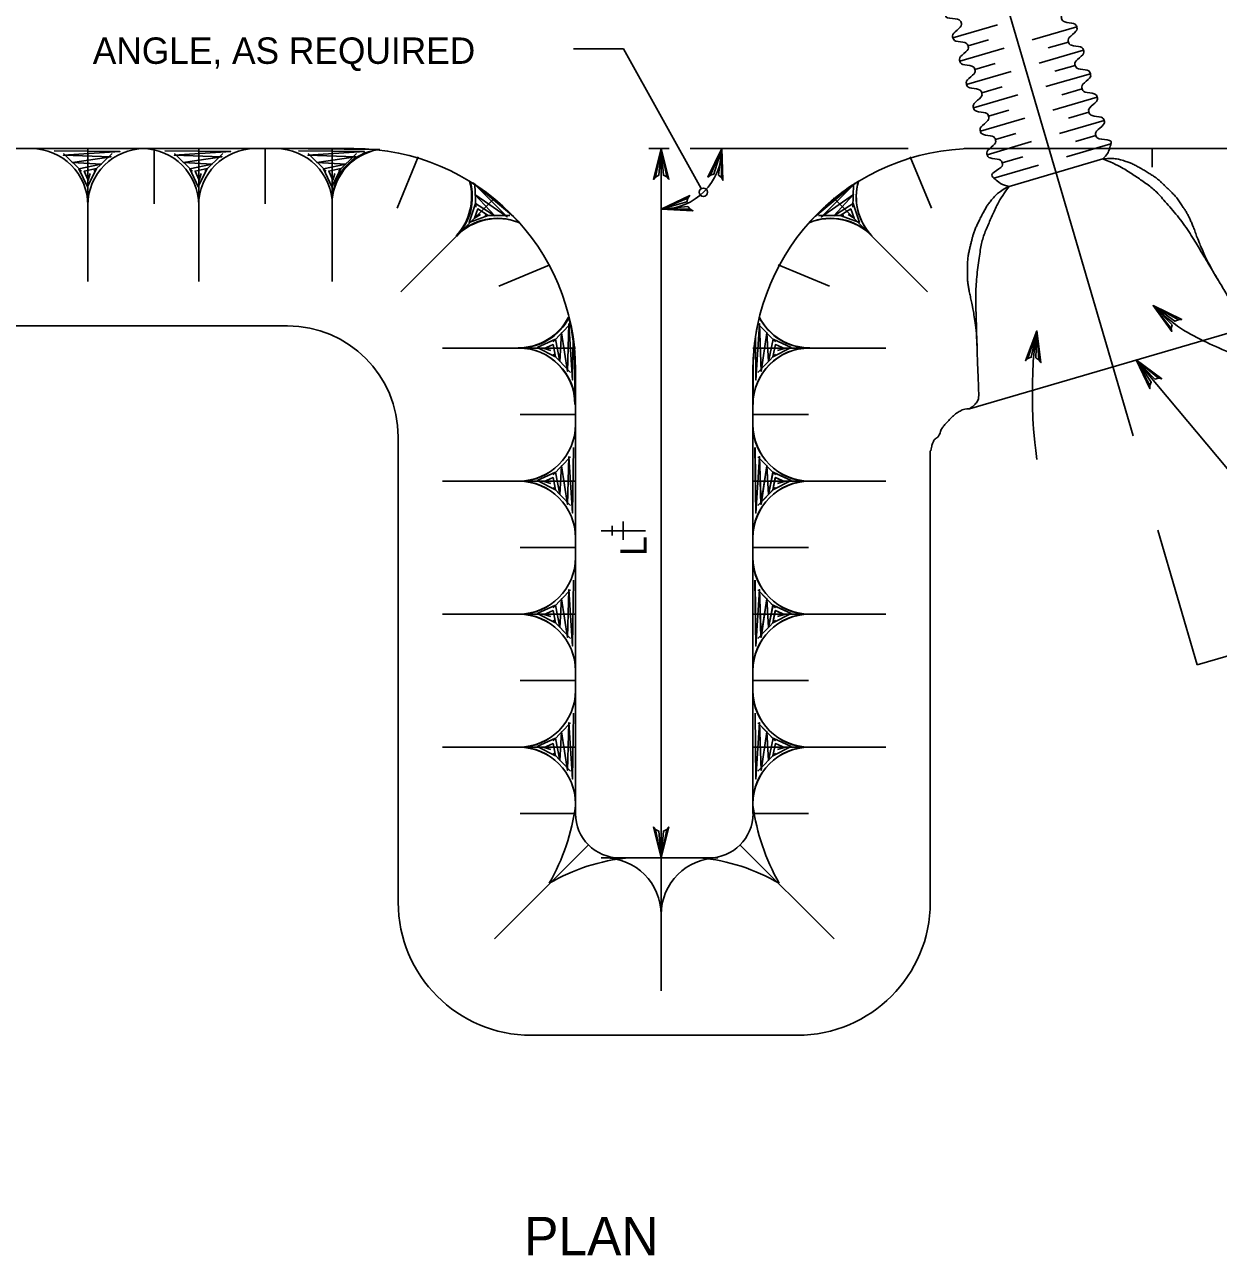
# Model space of a CAD drawing. Extents: x 636462 to 637367, y 299944 to 300538.
# Drawn here: x 636619.2 to 636754.8, y 300214.8 to 300354.6 of the extents above; entities that cross this region are included whole.
import ezdxf

# ---------------------------------------------------------------- set-up
doc = ezdxf.new("R2010")
doc.units = 0
doc.layers.add('1', color=7, linetype='Continuous')
doc.layers.add('Default', color=7, linetype='Continuous')

# ---------------------------------------------------------------- blocks, each defined once
blk = doc.blocks.new('SC9446')
at = {"layer": 'Default'}
blk.add_line((0, 0), (0, 0), dxfattribs=at)
blk = doc.blocks.new('CROSS')
at = {"layer": 'Default'}
for p, q in [((0, 0.436), (0, -0.435)), ((0, 0.436), (0, 0)), ((-0.182, 0), (0, 0)), ((-0.096, 0.218), (0, 0.218)), ((0, 0.218), (0.096, 0.218)), ((0, 0), (0.182, 0))]:
    blk.add_line(p, q, dxfattribs=at)

msp = doc.modelspace()

# ---------------------------------------------------------------- linework, layer by layer
at = {"layer": '1'}
for p, q in [((636686.8, 300259.95), (636685.04, 300259.95)), ((636696.87, 300259.95), (636686.8, 300259.95))]:
    msp.add_line(p, q, dxfattribs=at)
for centre, radius, start, end in [((636657.2, 300269.28), 24.8, 330.4999, 352.1576), ((636686.8, 300264.99), 5.04, 180, 270), ((636696.88, 300264.99), 5.04, 270, 0), ((636726.48, 300269.28), 24.8, 187.8423, 209.5001), ((636689.86, 300238.02), 22.04, 95.5213, 120.1887), ((636685.04, 300253.51), 6.44, 0, 90), ((636697.93, 300253.51), 6.44, 90, 180), ((636693.81, 300238.02), 22.04, 59.8113, 84.4787)]:
    msp.add_arc(centre, radius, start, end, dxfattribs=at)
at = {"layer": 'Default'}
for p, q in [((636730.38, 300358.11), (636745.08, 300307.89)), ((636724.62, 300353.13), (636729.68, 300354.61)), ((636733.63, 300352.88), (636738.69, 300354.36)), ((636726.34, 300352.19), (636728.66, 300352.87)), ((636725.4, 300350.47), (636730.45, 300351.95)), ((636734.41, 300350.22), (636739.46, 300351.7)), ((636735.43, 300351.96), (636737.75, 300352.64)), ((636727.12, 300349.53), (636729.44, 300350.21)), ((636736.21, 300349.31), (636738.52, 300349.99)), ((636726.18, 300347.82), (636731.23, 300349.29)), ((636735.19, 300347.57), (636740.24, 300349.04)), ((636727.9, 300346.88), (636730.22, 300347.55)), ((636736.99, 300346.65), (636739.3, 300347.33)), ((636726.96, 300345.16), (636732.01, 300346.64)), ((636735.97, 300344.91), (636741.02, 300346.39)), ((636728.68, 300344.22), (636730.99, 300344.89)), ((636737.76, 300343.99), (636740.08, 300344.67)), ((636727.74, 300342.5), (636732.79, 300343.98)), ((636736.75, 300342.25), (636741.8, 300343.73)), ((636729.45, 300341.56), (636731.77, 300342.24)), ((636738.54, 300341.33), (636740.86, 300342.01)), ((636589.35, 300340.53), (636632.71, 300340.53)), ((636632.81, 300340.53), (636619.57, 300340.53)), ((636619.57, 300340.53), (636619.93, 300340.53)), ((636626.37, 300340.53), (636626.37, 300325.42)), ((636645.4, 300340.53), (636632.16, 300340.53)), ((636632.16, 300340.53), (636632.52, 300340.53)), ((636632.71, 300340.53), (636656.58, 300340.53)), ((636633.92, 300340.53), (636633.92, 300334.24)), ((636638.96, 300340.53), (636638.96, 300325.42)), ((636646.51, 300340.53), (636646.51, 300334.24)), ((636659.53, 300340.42), (636647.34, 300340.53)), ((636647.34, 300340.53), (636647.7, 300340.53)), ((636654.14, 300340.53), (636654.14, 300325.42)), ((636692.38, 300340.53), (636690.08, 300340.53)), ((636691.49, 300340.53), (636691.49, 300259.95)), ((636719.55, 300340.53), (636694.79, 300340.53)), ((636725.91, 300340.53), (636841.16, 300340.53)), ((636727.09, 300340.53), (636738.5, 300340.53)), ((636728.51, 300339.84), (636733.57, 300341.32)), ((636737.53, 300339.59), (636742.58, 300341.07)), ((636747.24, 300340.53), (636747.24, 300338.43)), ((636623.61, 300339.97), (636625.66, 300337.98)), ((636629.13, 300339.97), (636627.07, 300337.98)), ((636636.2, 300339.97), (636638.25, 300337.98)), ((636641.72, 300339.97), (636639.66, 300337.98)), ((636651.38, 300339.97), (636653.43, 300337.98)), ((636656.9, 300339.97), (636654.85, 300337.98)), ((636663.9, 300339.58), (636661.49, 300333.76)), ((636719.78, 300339.58), (636722.19, 300333.76)), ((636730.23, 300338.9), (636732.55, 300339.58)), ((636731.01, 300336.24), (636741.64, 300339.35)), ((636729.29, 300337.18), (636734.34, 300338.66)), ((636670.33, 300336.45), (636670.43, 300333.89)), ((636713.35, 300336.45), (636713.25, 300333.89)), ((636672.52, 300334.85), (636661.93, 300324.25)), ((636711.07, 300334.94), (636721.75, 300324.25)), ((636674.31, 300332.95), (636671.45, 300332.92)), ((636709.37, 300332.95), (636712.23, 300332.92)), ((636678.77, 300327.27), (636673.07, 300324.9)), ((636704.79, 300327.31), (636710.61, 300324.9)), ((636681.2, 300320.63), (636679.21, 300318.58)), ((636702.48, 300320.63), (636704.46, 300318.58)), ((636589.35, 300320.39), (636649.03, 300320.39)), ((636726.5, 300310.97), (636759.06, 300320.5)), ((636681.77, 300317.87), (636666.66, 300317.87)), ((636701.91, 300317.87), (636717.02, 300317.87)), ((636681.2, 300315.11), (636679.21, 300317.16)), ((636702.48, 300315.11), (636704.46, 300317.16)), ((636681.7, 300315.38), (636681.7, 300311.46)), ((636681.77, 300315.35), (636681.77, 300264.99)), ((636701.91, 300315.35), (636701.91, 300264.99)), ((636701.92, 300315.38), (636701.92, 300311.46)), ((636681.77, 300310.31), (636675.47, 300310.31)), ((636681.77, 300296.3), (636681.77, 300309.54)), ((636681.77, 300309.54), (636681.77, 300309.18)), ((636701.89, 300296.3), (636701.89, 300309.54)), ((636701.89, 300309.54), (636701.89, 300309.18)), ((636701.91, 300310.31), (636708.21, 300310.31)), ((636661.62, 300307.8), (636661.62, 300254.92)), ((636681.2, 300305.52), (636679.21, 300303.47)), ((636681.2, 300305.52), (636679.21, 300303.47)), ((636702.48, 300305.52), (636704.46, 300303.47)), ((636722.06, 300306.19), (636722.06, 300254.92)), ((636681.77, 300302.76), (636666.66, 300302.76)), ((636701.91, 300302.76), (636717.02, 300302.76)), ((636681.2, 300300), (636679.21, 300302.05)), ((636702.46, 300300), (636704.44, 300302.05)), ((636702.48, 300300), (636704.46, 300302.05)), ((636747.9, 300297.2), (636752.38, 300281.88)), ((636681.77, 300295.21), (636675.47, 300295.21)), ((636681.77, 300281.19), (636681.77, 300294.43)), ((636681.77, 300294.43), (636681.77, 300294.07)), ((636701.89, 300281.19), (636701.89, 300294.43)), ((636701.89, 300294.43), (636701.89, 300294.07)), ((636701.91, 300295.21), (636708.21, 300295.21)), ((636681.2, 300290.41), (636679.21, 300288.36)), ((636681.2, 300290.41), (636679.21, 300288.36)), ((636702.46, 300290.41), (636704.44, 300288.36)), ((636702.46, 300290.41), (636704.44, 300288.36)), ((636702.48, 300290.41), (636704.46, 300288.36)), ((636681.77, 300287.65), (636666.66, 300287.65)), ((636701.91, 300287.65), (636717.02, 300287.65)), ((636681.2, 300284.89), (636679.21, 300286.95)), ((636702.48, 300284.89), (636704.46, 300286.95)), ((636752.38, 300281.88), (636762.67, 300284.89)), ((636681.77, 300280.1), (636675.47, 300280.1)), ((636701.91, 300280.1), (636708.21, 300280.1)), ((636681.77, 300266.08), (636681.77, 300279.32)), ((636681.77, 300279.32), (636681.77, 300278.96)), ((636701.89, 300266.08), (636701.89, 300279.32)), ((636701.89, 300279.32), (636701.89, 300278.96)), ((636681.2, 300275.3), (636679.21, 300273.25)), ((636702.46, 300275.3), (636704.44, 300273.25)), ((636702.48, 300275.3), (636704.46, 300273.25)), ((636681.77, 300272.54), (636666.66, 300272.54)), ((636681.2, 300269.79), (636679.21, 300271.84)), ((636701.91, 300272.54), (636717.02, 300272.54)), ((636702.48, 300269.79), (636704.46, 300271.84)), ((636681.77, 300264.99), (636675.47, 300264.99)), ((636701.91, 300264.99), (636701.91, 300265.89)), ((636701.91, 300264.99), (636708.21, 300264.99)), ((636683.24, 300261.43), (636672.56, 300250.74)), ((636700.44, 300261.43), (636711.12, 300250.74)), ((636697.93, 300259.95), (636684.68, 300259.95)), ((636684.68, 300259.95), (636685.04, 300259.95)), ((636686.8, 300259.95), (636687.74, 300259.95)), ((636686.8, 300259.95), (636687.74, 300259.95)), ((636691.49, 300259.95), (636691.49, 300244.84)), ((636695.93, 300259.95), (636696.88, 300259.95)), ((636676.73, 300239.81), (636706.95, 300239.81))]:
    msp.add_line(p, q, dxfattribs=at)
for points in [[(636696.04, 300335.99), (636687.2, 300351.85), (636681.53, 300351.85)], [(636622.53, 300340.29), (636630.01, 300340.19), (636623.59, 300339.78), (636629.01, 300339.61), (636624.62, 300338.94), (636627.89, 300338.75), (636625.36, 300338.24), (636626.32, 300336.18), (636627.35, 300338.27), (636625.97, 300337.98), (636626.42, 300336.95), (636626.64, 300337.72)], [(636635.12, 300340.29), (636642.6, 300340.19), (636636.18, 300339.78), (636641.6, 300339.61), (636637.21, 300338.94), (636640.48, 300338.75), (636637.95, 300338.24), (636638.91, 300336.18), (636639.94, 300338.27), (636638.56, 300337.98), (636639.01, 300336.95), (636639.23, 300337.72)], [(636650.31, 300340.29), (636657.78, 300340.19), (636651.37, 300339.78), (636656.79, 300339.61), (636652.39, 300338.94), (636655.66, 300338.75), (636653.13, 300338.24), (636654.09, 300336.18), (636655.12, 300338.27), (636653.74, 300337.98), (636654.19, 300336.95), (636654.41, 300337.72)], [(636690.85, 300337.3), (636690.63, 300337.03), (636691.49, 300340.53), (636690.85, 300337.3), (636691.22, 300337.5), (636691.49, 300340.53), (636691.74, 300337.5), (636692.12, 300337.32), (636691.49, 300340.53), (636692.37, 300337.04), (636692.12, 300337.32)], [(636697.08, 300337.51), (636696.8, 300337.29), (636698.38, 300340.53), (636697.08, 300337.51), (636697.48, 300337.62), (636698.38, 300340.53), (636698, 300337.52), (636698.33, 300337.26), (636698.38, 300340.53), (636698.51, 300336.93), (636698.33, 300337.26)], [(636674.71, 300332.83), (636670.17, 300336.62), (636673.99, 300332.77), (636670.34, 300335.31), (636672.58, 300332.91), (636670.39, 300334.29), (636669.67, 300332.14), (636671.85, 300332.94), (636670.65, 300333.68), (636670.27, 300332.63), (636670.96, 300333.03)], [(636708.97, 300332.83), (636713.51, 300336.62), (636709.69, 300332.77), (636713.34, 300335.31), (636711.1, 300332.91), (636713.29, 300334.29), (636714.01, 300332.14), (636711.83, 300332.94), (636713.03, 300333.68), (636713.41, 300332.63), (636712.72, 300333.03)], [(636694.78, 300333.64), (636695.09, 300333.48), (636691.49, 300333.64), (636694.78, 300333.64), (636694.51, 300333.97), (636691.49, 300333.64), (636694.41, 300334.48), (636694.51, 300334.89), (636691.49, 300333.64), (636694.74, 300335.19), (636694.51, 300334.89)], [(636749.42, 300320.11), (636749.48, 300319.76), (636747.37, 300322.69), (636749.42, 300320.11), (636749.51, 300320.52), (636747.37, 300322.69), (636749.85, 300320.92), (636750.23, 300321.09), (636747.37, 300322.69), (636750.61, 300321.1), (636750.23, 300321.09)], [(636681.49, 300319.08), (636681.43, 300314.23), (636681.01, 300320.64), (636680.85, 300315.22), (636680.18, 300319.62), (636679.98, 300316.35), (636679.47, 300318.88), (636677.42, 300317.92), (636679.5, 300316.89), (636679.21, 300318.27), (636678.19, 300317.82), (636678.96, 300317.6)], [(636702.19, 300319.08), (636702.25, 300314.23), (636702.67, 300320.64), (636702.83, 300315.22), (636703.5, 300319.62), (636703.69, 300316.35), (636704.21, 300318.88), (636706.26, 300317.92), (636704.17, 300316.89), (636704.46, 300318.27), (636705.49, 300317.82), (636704.72, 300317.6)], [(636733.14, 300316.67), (636732.88, 300316.43), (636734.16, 300319.81), (636733.14, 300316.67), (636733.53, 300316.82), (636734.16, 300319.81), (636734.05, 300316.77), (636734.4, 300316.54), (636734.16, 300319.81), (636734.62, 300316.23), (636734.4, 300316.54)], [(636745.45, 300316.52), (636758.15, 300301.36), (636763.81, 300301.36)], [(636747, 300313.61), (636747, 300313.26), (636745.45, 300316.52), (636747, 300313.61), (636747.16, 300314), (636745.45, 300316.52), (636747.57, 300314.34), (636747.97, 300314.44), (636745.45, 300316.52), (636748.35, 300314.38), (636747.97, 300314.44)], [(636681.52, 300306.59), (636681.43, 300299.12), (636681.01, 300305.53), (636680.85, 300300.11), (636680.18, 300304.51), (636679.98, 300301.24), (636679.47, 300303.77), (636677.42, 300302.81), (636679.5, 300301.78), (636679.21, 300303.16), (636678.19, 300302.71), (636678.96, 300302.49)], [(636702.13, 300306.59), (636702.23, 300299.12), (636702.65, 300305.53), (636702.81, 300300.11), (636703.48, 300304.51), (636703.67, 300301.24), (636704.19, 300303.77), (636706.24, 300302.81), (636704.16, 300301.78), (636704.44, 300303.16), (636705.47, 300302.71), (636704.7, 300302.49)], [(636702.15, 300306.59), (636702.25, 300299.12), (636702.67, 300305.53), (636702.83, 300300.11), (636703.5, 300304.51), (636703.69, 300301.24), (636704.21, 300303.77), (636706.26, 300302.81), (636704.17, 300301.78), (636704.46, 300303.16), (636705.49, 300302.71), (636704.72, 300302.49)], [(636681.52, 300291.49), (636681.43, 300284.01), (636681.01, 300290.43), (636680.85, 300285), (636680.18, 300289.4), (636679.98, 300286.13), (636679.47, 300288.66), (636677.42, 300287.7), (636679.5, 300286.67), (636679.21, 300288.05), (636678.19, 300287.6), (636678.96, 300287.38)], [(636702.13, 300291.49), (636702.23, 300284.01), (636702.65, 300290.43), (636702.81, 300285), (636703.48, 300289.4), (636703.67, 300286.13), (636704.19, 300288.66), (636706.24, 300287.7), (636704.16, 300286.67), (636704.44, 300288.05), (636705.47, 300287.6), (636704.7, 300287.38)], [(636702.15, 300291.49), (636702.25, 300284.01), (636702.67, 300290.43), (636702.83, 300285), (636703.5, 300289.4), (636703.69, 300286.13), (636704.21, 300288.66), (636706.26, 300287.7), (636704.17, 300286.67), (636704.46, 300288.05), (636705.49, 300287.6), (636704.72, 300287.38)], [(636681.52, 300276.38), (636681.43, 300268.9), (636681.01, 300275.32), (636680.85, 300269.9), (636680.18, 300274.29), (636679.98, 300271.02), (636679.47, 300273.55), (636677.42, 300272.59), (636679.5, 300271.56), (636679.21, 300272.94), (636678.19, 300272.49), (636678.96, 300272.27)], [(636702.15, 300276.38), (636702.25, 300268.9), (636702.67, 300275.32), (636702.83, 300269.9), (636703.5, 300274.29), (636703.69, 300271.02), (636704.21, 300273.55), (636706.26, 300272.59), (636704.17, 300271.56), (636704.46, 300272.94), (636705.49, 300272.49), (636704.72, 300272.27)], [(636692.12, 300263.18), (636692.35, 300263.45), (636691.49, 300259.95), (636692.12, 300263.18), (636691.75, 300262.99), (636691.49, 300259.95), (636691.23, 300262.98), (636690.85, 300263.16), (636691.49, 300259.95), (636690.6, 300263.45), (636690.85, 300263.16)]]:
    msp.add_lwpolyline(points, dxfattribs=at)
msp.add_circle((636696.28, 300335.57), 0.481, dxfattribs=at)
for centre, radius, start, end in [((636619.93, 300334.09), 6.44, 0, 90), ((636619.93, 300334.09), 6.44, 0, 90), ((636632.81, 300334.09), 6.44, 90, 180), ((636632.81, 300334.09), 6.44, 90, 180), ((636632.81, 300334.09), 6.44, 90, 180), ((636632.81, 300334.09), 6.44, 90, 180), ((636632.52, 300334.09), 6.44, 0, 90), ((636632.52, 300334.09), 6.44, 0, 90), ((636645.4, 300334.09), 6.44, 90, 180), ((636645.4, 300334.09), 6.44, 90, 180), ((636647.7, 300334.09), 6.44, 0, 90), ((636660.51, 300334.09), 6.44, 101.7661, 173.8515), ((636660, 300334.56), 5.88, 94.5668, 184.5668), ((636656.59, 300315.35), 25.18, 0, 90), ((636691.49, 300340.53), 6.9, 270, 0), ((636727.09, 300315.35), 25.18, 90, 180), ((636663.52, 300335.06), 6.44, 316.4347, 15.8913), ((636663.6, 300335.03), 6.44, 316.4347, 15.8913), ((636656.52, 300315.38), 25.18, 41.7104, 58.3729), ((636727.1, 300315.38), 25.18, 121.6271, 138.2896), ((636720.08, 300335.03), 6.44, 164.1087, 223.5653), ((636720.09, 300335.06), 6.44, 164.1087, 223.5653), ((636672.86, 300326.18), 6.44, 67.6038, 136.4347), ((636672.93, 300326.15), 6.44, 67.6038, 136.4347), ((636710.76, 300326.18), 6.44, 43.5653, 112.3962), ((636710.75, 300326.15), 6.44, 43.5653, 112.3962), ((636675.25, 300324.34), 6.44, 270, 332.5918), ((636675.32, 300324.31), 6.44, 270, 332.5918), ((636656.52, 300315.38), 25.18, 360, 13.7705), ((636727.1, 300315.38), 25.18, 166.2295, 180), ((636708.35, 300324.31), 6.44, 207.4082, 270), ((636708.36, 300324.34), 6.44, 207.4082, 270), ((636649.03, 300307.8), 12.59, 0, 90), ((636675.25, 300311.46), 6.44, 0, 90), ((636675.32, 300311.43), 6.44, 0, 90), ((636708.35, 300311.43), 6.44, 90, 180), ((636708.36, 300311.46), 6.44, 90, 180), ((636675.32, 300309.2), 6.44, 270, 0), ((636675.32, 300309.2), 6.44, 270, 0), ((636675.32, 300309.18), 6.44, 270, 360), ((636708.33, 300309.18), 6.44, 180, 270), ((636708.35, 300309.2), 6.44, 180, 270), ((636675.32, 300296.32), 6.44, 0, 90), ((636675.32, 300296.3), 6.44, 360, 90), ((636708.33, 300296.32), 6.44, 90, 180), ((636708.33, 300296.3), 6.44, 90, 180), ((636708.35, 300296.32), 6.44, 90, 180), ((636675.32, 300294.09), 6.44, 270, 0), ((636675.32, 300294.09), 6.44, 270, 0), ((636675.32, 300294.07), 6.44, 270, 360), ((636708.33, 300294.09), 6.44, 180, 270), ((636708.33, 300294.09), 6.44, 180, 270), ((636708.33, 300294.07), 6.44, 180, 270), ((636708.35, 300294.09), 6.44, 180, 270), ((636675.32, 300281.21), 6.44, 0, 90), ((636675.32, 300281.19), 6.44, 360, 90), ((636708.33, 300281.19), 6.44, 90, 180), ((636708.35, 300281.21), 6.44, 90, 180), ((636675.32, 300278.98), 6.44, 270, 0), ((636675.32, 300278.96), 6.44, 270, 360), ((636708.33, 300278.98), 6.44, 180, 270), ((636708.33, 300278.96), 6.44, 180, 270), ((636708.35, 300278.98), 6.44, 180, 270), ((636675.32, 300266.1), 6.44, 0, 90), ((636675.32, 300266.08), 6.44, 360, 90), ((636708.33, 300266.08), 6.44, 90, 180), ((636708.35, 300266.1), 6.44, 90, 180), ((636657.2, 300269.28), 24.8, 330.4999, 352.1577), ((636657.2, 300269.28), 24.8, 330.4999, 352.1576), ((636686.8, 300264.99), 5.04, 180, 270), ((636686.8, 300264.99), 5.04, 180, 270), ((636696.88, 300264.99), 5.04, 270, 0), ((636726.48, 300269.28), 24.8, 187.8423, 209.5001), ((636689.86, 300238.02), 22.04, 95.5213, 120.1887), ((636685.04, 300253.51), 6.44, 0, 90), ((636676.73, 300254.92), 15.11, 180, 270), ((636706.95, 300254.92), 15.11, 270, 0)]:
    msp.add_arc(centre, radius, start, end, dxfattribs=at)
for points in [[(636735.41, 300360.62), (636736.07, 300360.52), (636736.63, 300360.13), (636737.13, 300359.68), (636737.63, 300359.23), (636736.06, 300358.4), (636736.19, 300357.96), (636736.32, 300357.52), (636737.78, 300357.46), (636737.91, 300357.02), (636738.04, 300356.58), (636736.84, 300355.74), (636736.97, 300355.3), (636737.1, 300354.86), (636738.56, 300354.8), (636738.69, 300354.36), (636738.82, 300353.92), (636737.62, 300353.08), (636737.75, 300352.64), (636737.88, 300352.2), (636739.33, 300352.14), (636739.46, 300351.7), (636739.59, 300351.26), (636738.39, 300350.43), (636738.52, 300349.99), (636738.65, 300349.54), (636740.11, 300349.49), (636740.24, 300349.04), (636740.37, 300348.6), (636739.17, 300347.77), (636739.3, 300347.33), (636739.43, 300346.88), (636740.89, 300346.83), (636741.02, 300346.39), (636741.15, 300345.94), (636739.95, 300345.11), (636740.08, 300344.67), (636740.21, 300344.22), (636741.67, 300344.17), (636741.8, 300343.73), (636741.93, 300343.28), (636740.73, 300342.45), (636740.86, 300342.01), (636740.99, 300341.57), (636742.71, 300341.53), (636742.58, 300341.07), (636742.44, 300340.61), (636742.16, 300339.77), (636741.64, 300339.35)], [(636724.79, 300357.51), (636724.26, 300357.09), (636723.98, 300356.25), (636723.85, 300355.79), (636723.71, 300355.33), (636725.43, 300355.29), (636725.56, 300354.85), (636725.69, 300354.41), (636724.49, 300353.57), (636724.62, 300353.13), (636724.75, 300352.69), (636726.21, 300352.63), (636726.34, 300352.19), (636726.47, 300351.75), (636725.27, 300350.91), (636725.4, 300350.47), (636725.53, 300350.03), (636726.99, 300349.97), (636727.12, 300349.53), (636727.25, 300349.09), (636726.05, 300348.26), (636726.18, 300347.82), (636726.31, 300347.37), (636727.77, 300347.32), (636727.9, 300346.88), (636728.03, 300346.43), (636726.83, 300345.6), (636726.96, 300345.16), (636727.09, 300344.71), (636728.55, 300344.66), (636728.68, 300344.22), (636728.81, 300343.77), (636727.61, 300342.94), (636727.74, 300342.5), (636727.87, 300342.05), (636729.32, 300342), (636729.45, 300341.56), (636729.58, 300341.11), (636728.38, 300340.28), (636728.51, 300339.84), (636728.64, 300339.4), (636730.1, 300339.34), (636730.23, 300338.9), (636730.36, 300338.46), (636728.79, 300337.63), (636729.29, 300337.18), (636729.79, 300336.73), (636730.36, 300336.34), (636731.01, 300336.24)], [(636741.64, 300339.35), (636742.43, 300339.44), (636743.27, 300339.39), (636744.06, 300339.15), (636744.52, 300339.01), (636744.96, 300338.84), (636745.38, 300338.61), (636745.87, 300338.34), (636746.35, 300338.07), (636746.83, 300337.77), (636747.22, 300337.52), (636747.61, 300337.28), (636747.97, 300336.99), (636748.26, 300336.74), (636748.53, 300336.47), (636748.81, 300336.21), (636749.14, 300335.89), (636749.47, 300335.58), (636749.77, 300335.24), (636750.14, 300334.84), (636750.43, 300334.38), (636750.73, 300333.92), (636750.95, 300333.61), (636751.16, 300333.29), (636751.33, 300332.96), (636751.54, 300332.57), (636751.71, 300332.16), (636751.88, 300331.76), (636752.11, 300331.18), (636752.3, 300330.59), (636752.54, 300330.01), (636753.17, 300328.48), (636753.9, 300327.01), (636754.76, 300325.58)], [(636741.64, 300339.35), (636742.92, 300338.86), (636744.06, 300338.26), (636745.19, 300337.5), (636746.41, 300336.69), (636747.55, 300335.86), (636748.51, 300334.77), (636749.97, 300333.1), (636751.29, 300331.37), (636752.42, 300329.49), (636753.2, 300328.19), (636753.98, 300326.89), (636754.76, 300325.58), (636755.62, 300324.16), (636756.43, 300322.72), (636757.3, 300321.28), (636757.64, 300320.73), (636758.52, 300320.36), (636759.06, 300320.5)], [(636731.01, 300336.24), (636730.27, 300335.87), (636729.62, 300335.4), (636729.08, 300334.77), (636728.76, 300334.4), (636728.49, 300334.02), (636728.26, 300333.6), (636727.99, 300333.11), (636727.73, 300332.62), (636727.49, 300332.11), (636727.3, 300331.69), (636727.09, 300331.28), (636726.95, 300330.84), (636726.84, 300330.47), (636726.76, 300330.1), (636726.67, 300329.72), (636726.56, 300329.28), (636726.45, 300328.85), (636726.37, 300328.4), (636726.29, 300327.85), (636726.29, 300327.31), (636726.28, 300326.76), (636726.27, 300326.39), (636726.26, 300326.01), (636726.29, 300325.63), (636726.33, 300325.19), (636726.4, 300324.76), (636726.48, 300324.32), (636726.6, 300323.71), (636726.75, 300323.11), (636726.87, 300322.5), (636727.16, 300320.86), (636727.34, 300319.21), (636727.38, 300317.57)], [(636731.01, 300336.24), (636730.2, 300335.14), (636729.56, 300334.01), (636729.02, 300332.77), (636728.43, 300331.43), (636727.91, 300330.1), (636727.69, 300328.67), (636727.37, 300326.49), (636727.19, 300324.31), (636727.25, 300322.12), (636727.29, 300320.61), (636727.33, 300319.09), (636727.38, 300317.57), (636727.43, 300315.9), (636727.51, 300314.24), (636727.56, 300312.58), (636727.57, 300311.94), (636727.07, 300311.35), (636726.5, 300310.97)], [(636763.67, 300316.37), (636760.62, 300316.14), (636757.45, 300316.7), (636754.43, 300318.07), (636751.71, 300319.3), (636749.48, 300320.72), (636747.37, 300322.69)], [(636734.16, 300305.22), (636733.77, 300308.13), (636733.63, 300311.06), (636733.68, 300313.97), (636733.7, 300315.92), (636733.87, 300317.86), (636734.16, 300319.81)], [(636726.5, 300310.97), (636726.07, 300310.97), (636725.64, 300310.85), (636725.22, 300310.59), (636724.81, 300310.33), (636724.54, 300310.05), (636724.23, 300309.74), (636723.92, 300309.42), (636723.62, 300309.1), (636723.38, 300308.74), (636723.23, 300308.53), (636723.21, 300308.25), (636723.09, 300308.03), (636722.91, 300307.72), (636722.52, 300307.53), (636722.38, 300307.18), (636722.25, 300306.86), (636722.16, 300306.53), (636722.1, 300306.19)]]:
    msp.add_open_spline(points, degree=3, dxfattribs=at)

# ---------------------------------------------------------------- block references
at = {"layer": 'Default', "xscale": 5.777458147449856, "yscale": 5.777458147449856, "rotation": 90.00000000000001}
msp.add_blockref('CROSS', (636687.19, 300297.12), dxfattribs=at)
at = {"layer": 'Default', "xscale": 2.753831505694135, "yscale": 2.753831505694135}
msp.add_blockref('SC9446', (636691.84, 300259.95), dxfattribs=at)

# ---------------------------------------------------------------- texts
at = {"layer": 'Default'}
for s, height, p in [('ANGLE, AS REQUIRED', 2.998, (636626.93, 300350.16)), ('PLAN', 4.372, (636675.92, 300214.8))]:
    msp.add_text(s, height=height, dxfattribs=at).set_placement(p)
msp.add_text('L', height=3, rotation=90, dxfattribs=at).set_placement((636689.84, 300294.27))

doc.saveas('drawing.dxf')
